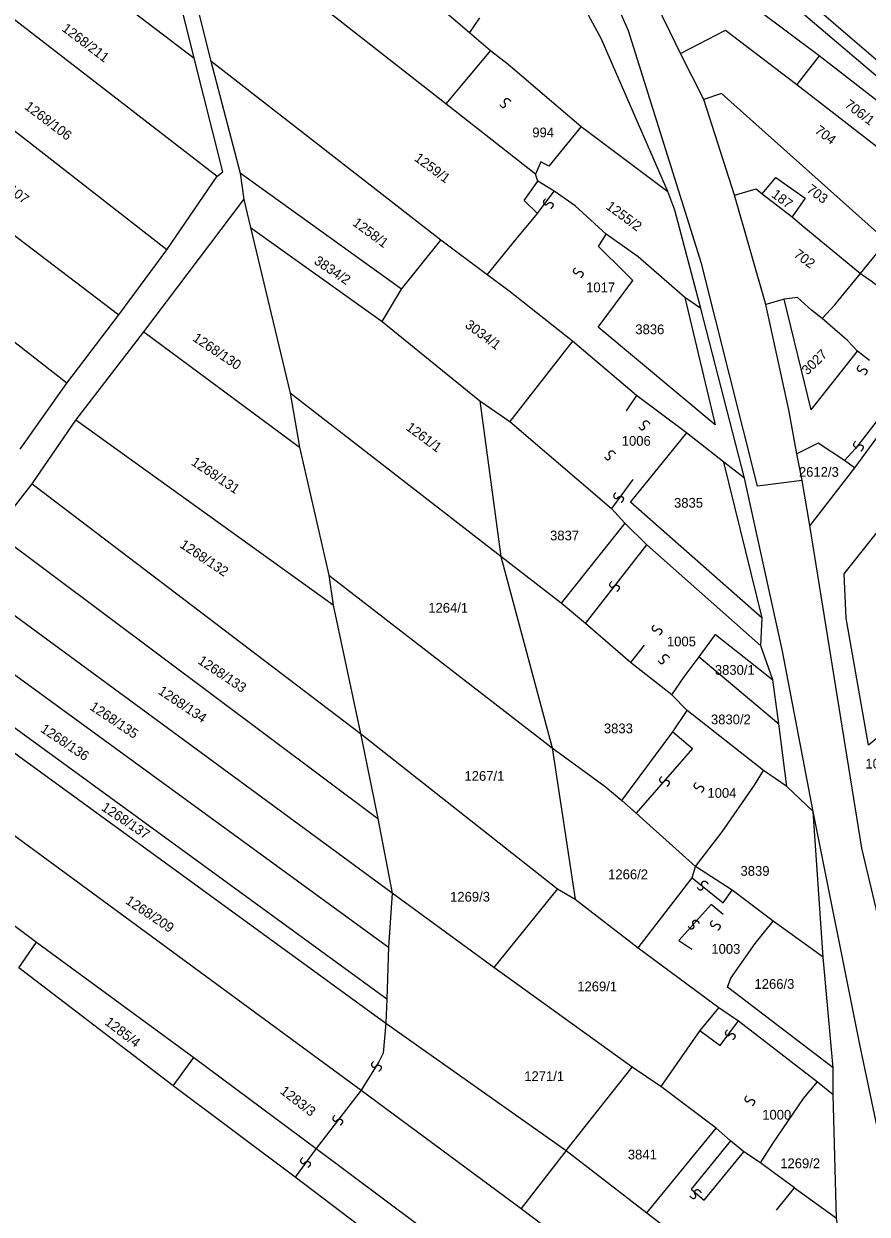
# Model space of a CAD drawing. Extents: x -581999 to -572728, y -1219553 to -1212032.
# Drawn here: x -577907.8 to -577734.8, y -1215058.5 to -1214814.1 of the extents above; entities that cross this region are included whole.
import ezdxf

# ---------------------------------------------------------------- set-up
doc = ezdxf.new("R2010")
doc.units = 0
for name, color, linetype in [('Vrstva 1', 7, 'Continuous'), ('Vrstva 2', 7, 'Continuous'), ('Vrstva 4', 7, 'Continuous'), ('Vrstva 6', 7, 'Continuous')]:
    doc.layers.add(name, color=color, linetype=linetype)

msp = doc.modelspace()

# ---------------------------------------------------------------- linework, layer by layer
at = {"layer": 'Vrstva 1'}
for p, q in [((-577805.154, -1214850.428), (-577802.393, -1214846.429)), ((-577802.455, -1214853.067), (-577805.154, -1214850.428)), ((-577769.288, -1214944.062), (-577752.916, -1214957.844)), ((-577744.997, -1215031.305), (-577741.783, -1215033.863)), ((-577838.633, -1215032.986), (-577805.767, -1215057.281)), ((-577796.548, -1215045.385), (-577805.767, -1215057.281)), ((-577749.734, -1215053.023), (-577741.1, -1215059.241)), ((-577805.767, -1215057.281), (-577776.782, -1215079.289))]:
    msp.add_line(p, q, dxfattribs=at)
for points in [[(-577872.881, -1214821.167), (-577881.879, -1214784.766), (-577891.885, -1214776.612), (-577906.301, -1214795.655)], [(-577821.28, -1214830.565), (-577878.507, -1214785.689)], [(-577878.507, -1214785.689), (-577869.457, -1214821.833)], [(-577717.101, -1214835.147), (-577773.13, -1214787)], [(-577906.301, -1214795.655), (-577872.881, -1214821.167)], [(-577789.366, -1214817.133), (-577800.849, -1214795.966)], [(-577770.074, -1214801.603), (-577765.899, -1214796.69), (-577721.694, -1214834.344), (-577718.663, -1214836.797)], [(-577744.685, -1214820.71), (-577770.074, -1214801.603)], [(-577775.319, -1214815.749), (-577778.369, -1214809.409), (-577781.422, -1214803.251)], [(-577916.139, -1214808.272), (-577868.169, -1214845.419)], [(-577824.804, -1214808.7), (-577816.402, -1214815.913)], [(-577816.402, -1214815.913), (-577812.087, -1214819.635)], [(-577775.677, -1214848.564), (-577789.366, -1214817.133)], [(-577773.096, -1214820.208), (-577775.319, -1214815.749)], [(-577773.096, -1214820.208), (-577763.871, -1214815.445), (-577749.226, -1214826.599)], [(-577812.087, -1214819.635), (-577821.28, -1214830.565)], [(-577812.087, -1214819.635), (-577808.453, -1214822.43)], [(-577768.339, -1214829.671), (-577773.096, -1214820.208)], [(-577868.169, -1214845.419), (-577867.027, -1214844.505), (-577872.881, -1214821.167)], [(-577869.457, -1214821.833), (-577863.423, -1214844.776)], [(-577822.295, -1214858.556), (-577869.457, -1214821.833)], [(-577808.453, -1214822.43), (-577793.468, -1214835.222)], [(-577744.685, -1214820.71), (-577749.226, -1214826.599)], [(-577720.879, -1214839.207), (-577744.685, -1214820.71)], [(-577878.466, -1214860.562), (-577926.666, -1214822.96)], [(-577749.226, -1214826.599), (-577723.731, -1214846.371)], [(-577730.767, -1214858.778), (-577764.668, -1214828.469), (-577768.339, -1214829.671)], [(-577762.008, -1214849.341), (-577768.339, -1214829.671)], [(-577802.883, -1214844.996), (-577821.28, -1214830.565)], [(-577937.19, -1214836.724), (-577888.302, -1214873.863)], [(-577793.468, -1214835.222), (-577800.128, -1214843.356), (-577801.768, -1214842.475)], [(-577793.468, -1214835.222), (-577775.677, -1214848.564)], [(-577801.768, -1214842.475), (-577802.883, -1214844.996)], [(-577878.466, -1214860.562), (-577868.169, -1214845.419)], [(-577830.352, -1214868.618), (-577863.423, -1214844.776)], [(-577863.423, -1214844.776), (-577862.722, -1214850.232)], [(-577799.024, -1214848.482), (-577802.393, -1214846.429), (-577802.883, -1214844.996)], [(-577756.338, -1214849.025), (-577753.571, -1214845.72), (-577747.56, -1214849.959), (-577750.211, -1214853.736)], [(-577794.71, -1214851.511), (-577799.024, -1214848.482)], [(-577768.947, -1214872.584), (-577774.255, -1214852.389), (-577775.677, -1214848.564)], [(-577762.008, -1214849.341), (-577757.6, -1214848.009), (-577756.338, -1214849.025)], [(-577755.598, -1214871.752), (-577762.008, -1214849.341)], [(-577756.338, -1214849.025), (-577750.211, -1214853.736)], [(-577898.986, -1214887.922), (-577947.403, -1214850.101)], [(-577883.226, -1214877.35), (-577862.722, -1214850.232)], [(-577862.722, -1214850.232), (-577861.33, -1214855.947)], [(-577788.355, -1214857.319), (-577794.71, -1214851.511)], [(-577806.799, -1214858.337), (-577802.455, -1214853.067)], [(-577750.211, -1214853.736), (-577748.23, -1214855.49)], [(-577861.33, -1214855.947), (-577834.338, -1214875.209)], [(-577861.33, -1214855.947), (-577853.18, -1214889.973)], [(-577748.23, -1214855.49), (-577736.161, -1214865.367)], [(-577830.352, -1214868.618), (-577822.295, -1214858.556)], [(-577812.743, -1214865.669), (-577822.295, -1214858.556)], [(-577812.743, -1214865.669), (-577806.799, -1214858.337)], [(-577789.957, -1214859.843), (-577788.355, -1214857.319)], [(-577781.771, -1214861.977), (-577788.355, -1214857.319)], [(-577736.161, -1214865.367), (-577730.767, -1214858.778)], [(-577888.302, -1214873.863), (-577878.466, -1214860.562)], [(-577784.584, -1214865.104), (-577789.957, -1214859.843)], [(-577772.241, -1214870.342), (-577781.771, -1214861.977)], [(-577808.33, -1214868.935), (-577812.743, -1214865.669)], [(-577790.014, -1214876.435), (-577782.896, -1214866.833), (-577784.584, -1214865.104)], [(-577741.431, -1214871.84), (-577736.161, -1214865.367)], [(-577736.161, -1214865.367), (-577735.06, -1214866.132)], [(-577735.06, -1214866.132), (-577733.959, -1214866.896), (-577726.213, -1214872.899)], [(-577834.338, -1214875.209), (-577830.352, -1214868.618)], [(-577795.272, -1214879.265), (-577808.33, -1214868.935)], [(-577772.241, -1214870.342), (-577765.961, -1214896.423), (-577790.014, -1214876.435)], [(-577768.947, -1214872.584), (-577772.241, -1214870.342)], [(-577751.809, -1214870.652), (-577755.598, -1214871.752)], [(-577746.217, -1214872.888), (-577749.098, -1214870.305), (-577751.809, -1214870.652)], [(-577746.292, -1214893.355), (-577751.809, -1214870.652)], [(-577898.986, -1214887.922), (-577888.302, -1214873.863)], [(-577759.948, -1214907.393), (-577768.947, -1214872.584)], [(-577749.214, -1214902.401), (-577750.888, -1214893.394), (-577755.598, -1214871.752)], [(-577744.054, -1214874.641), (-577746.217, -1214872.888)], [(-577744.054, -1214874.641), (-577741.431, -1214871.84)], [(-577834.338, -1214875.209), (-577814.262, -1214891.549)], [(-577738.832, -1214879.162), (-577744.054, -1214874.641)], [(-577897.176, -1214895.462), (-577883.226, -1214877.35)], [(-577883.226, -1214877.35), (-577851.24, -1214901.065)], [(-577795.272, -1214879.265), (-577808.13, -1214895.741)], [(-577782.109, -1214890.419), (-577795.272, -1214879.265)], [(-577746.292, -1214893.355), (-577736.764, -1214881.349)], [(-577736.764, -1214881.349), (-577738.832, -1214879.162)], [(-577734.33, -1214883.219), (-577736.764, -1214881.349)], [(-577908.594, -1214901.454), (-577898.986, -1214887.922)], [(-577809.986, -1214923.459), (-577853.18, -1214889.973)], [(-577853.18, -1214889.973), (-577851.24, -1214901.065)], [(-577771.896, -1214898.095), (-577782.109, -1214890.419)], [(-577726.097, -1214889.907), (-577737.394, -1214905.307)], [(-577814.262, -1214891.549), (-577808.13, -1214895.741)], [(-577814.262, -1214891.549), (-577809.986, -1214923.459)], [(-577906.098, -1214908.537), (-577897.176, -1214895.462)], [(-577844.378, -1214933.467), (-577897.176, -1214895.462)], [(-577808.13, -1214895.741), (-577787.252, -1214913.628)], [(-577771.896, -1214898.095), (-577783.379, -1214912.272), (-577756.365, -1214936.081)], [(-577764.181, -1214904.139), (-577771.896, -1214898.095)], [(-577744.872, -1214900.225), (-577749.214, -1214902.401)], [(-577739.465, -1214903.76), (-577744.872, -1214900.225)], [(-577851.24, -1214901.065), (-577845.255, -1214927.289)], [(-577748.112, -1214907.863), (-577749.214, -1214902.401)], [(-577756.365, -1214936.081), (-577764.181, -1214904.139)], [(-577759.948, -1214907.393), (-577764.181, -1214904.139)], [(-577737.394, -1214905.307), (-577746.549, -1214917.111)], [(-577737.394, -1214905.307), (-577739.465, -1214903.76)], [(-577745.87, -1214975.785), (-577752.202, -1214942.91), (-577759.948, -1214907.393)], [(-577746.549, -1214917.111), (-577748.112, -1214907.863)], [(-577913.873, -1214918.393), (-577906.098, -1214908.537)], [(-577906.098, -1214908.537), (-577838.722, -1214959.823)], [(-577721.217, -1214951.277), (-577734.554, -1214962.178), (-577739.113, -1214936.121), (-577739.514, -1214927.04), (-577725.038, -1214908.739)], [(-577787.252, -1214913.628), (-577784.532, -1214916.641)], [(-577784.532, -1214916.641), (-577797.58, -1214933.029)], [(-577784.532, -1214916.641), (-577779.996, -1214921.049)], [(-577725.151, -1215028.582), (-577735.904, -1214983.329), (-577746.549, -1214917.111)], [(-577913.873, -1214918.393), (-577835.19, -1214977.265)], [(-577779.996, -1214921.049), (-577756.613, -1214941.836)], [(-577797.58, -1214933.029), (-577809.986, -1214923.459)], [(-577809.986, -1214923.459), (-577799.455, -1214962.724)], [(-577832.228, -1214992.583), (-577920.733, -1214927.564)], [(-577845.255, -1214927.289), (-577799.455, -1214962.724)], [(-577845.255, -1214927.289), (-577844.378, -1214933.467)], [(-577844.378, -1214933.467), (-577838.722, -1214959.823)], [(-577792.588, -1214937.209), (-577797.58, -1214933.029)], [(-577926.452, -1214935.59), (-577832.981, -1215003.643)], [(-577774.893, -1214951.838), (-577783.351, -1214945.243), (-577792.588, -1214937.209)], [(-577756.613, -1214941.836), (-577756.365, -1214936.081)], [(-577772.331, -1214948.175), (-577769.288, -1214944.062), (-577765.931, -1214939.469)], [(-577765.931, -1214939.469), (-577754.136, -1214948.76)], [(-577754.136, -1214948.76), (-577756.613, -1214941.836)], [(-577833.373, -1215014.342), (-577931.711, -1214942.697)], [(-577934.388, -1214945.892), (-577833.569, -1215019.238)], [(-577774.893, -1214951.838), (-577772.331, -1214948.175)], [(-577751.305, -1214970.645), (-577752.916, -1214957.844), (-577754.136, -1214948.76)], [(-577771.72, -1214955.083), (-577774.893, -1214951.838)], [(-577942.23, -1214956.913), (-577838.633, -1215032.986)], [(-577774.645, -1214959.44), (-577771.72, -1214955.083)], [(-577756.069, -1214967.39), (-577771.72, -1214955.083)], [(-577785.145, -1214973.548), (-577774.645, -1214959.44)], [(-577838.722, -1214959.823), (-577798.346, -1214991.679)], [(-577838.722, -1214959.823), (-577835.19, -1214977.265)], [(-577799.455, -1214962.724), (-577788.541, -1214970.706)], [(-577799.455, -1214962.724), (-577794.712, -1214993.776)], [(-577950.919, -1214968.374), (-577905.234, -1215002.63)], [(-577757.899, -1214970.37), (-577756.069, -1214967.39)], [(-577751.305, -1214970.645), (-577756.069, -1214967.39)], [(-577788.541, -1214970.706), (-577785.145, -1214973.548)], [(-577764.529, -1214979.993), (-577757.899, -1214970.37)], [(-577745.87, -1214975.785), (-577751.305, -1214970.645)], [(-577785.145, -1214973.548), (-577782.229, -1214976.12)], [(-577782.229, -1214976.12), (-577779.392, -1214978.712)], [(-577743.829, -1215005.717), (-577745.87, -1214975.785)], [(-577723.919, -1215082.491), (-577736.309, -1215023.635), (-577745.87, -1214975.785)], [(-577835.19, -1214977.265), (-577832.228, -1214992.583)], [(-577779.392, -1214978.712), (-577770.013, -1214987.092)], [(-577770.013, -1214987.092), (-577764.529, -1214979.993)], [(-577770.703, -1214989.389), (-577770.013, -1214987.092)], [(-577762.525, -1214991.974), (-577770.013, -1214987.092)], [(-577781.781, -1215003.757), (-577770.703, -1214989.389)], [(-577832.228, -1214992.583), (-577832.981, -1215003.643)], [(-577811.392, -1215007.847), (-577832.228, -1214992.583)], [(-577798.346, -1214991.679), (-577811.392, -1215007.847)], [(-577798.346, -1214991.679), (-577794.712, -1214993.776)], [(-577754.114, -1214998.324), (-577762.525, -1214991.974)], [(-577794.712, -1214993.776), (-577781.781, -1215003.757)], [(-577757.769, -1215002.902), (-577754.114, -1214998.324)], [(-577743.829, -1215005.717), (-577754.114, -1214998.324)], [(-577908.852, -1215007.879), (-577905.234, -1215002.63)], [(-577905.234, -1215002.63), (-577872.974, -1215026.324)], [(-577762.797, -1215010.002), (-577757.769, -1215002.902)], [(-577832.981, -1215003.643), (-577833.373, -1215014.342)], [(-577781.781, -1215003.757), (-577765.223, -1215016.061)], [(-577741.763, -1215028.425), (-577743.829, -1215005.717)], [(-577877.169, -1215032.139), (-577908.852, -1215007.879)], [(-577783.029, -1215028.281), (-577811.392, -1215007.847)], [(-577741.763, -1215028.425), (-577763.485, -1215011.839), (-577762.797, -1215010.002)], [(-577833.373, -1215014.342), (-577833.569, -1215019.238)], [(-577765.223, -1215016.061), (-577769.148, -1215020.777)], [(-577765.223, -1215016.061), (-577761.237, -1215018.756)], [(-577833.569, -1215019.238), (-577796.548, -1215045.385)], [(-577761.237, -1215018.756), (-577744.997, -1215031.305)], [(-577769.148, -1215020.777), (-577777.13, -1215032.23)], [(-577877.169, -1215032.139), (-577872.974, -1215026.324)], [(-577872.974, -1215026.324), (-577847.84, -1215044.937), (-577785.524, -1215091.587)], [(-577796.548, -1215045.385), (-577783.029, -1215028.281)], [(-577777.13, -1215032.23), (-577783.029, -1215028.281)], [(-577741.783, -1215033.863), (-577741.763, -1215028.425)], [(-577775.2, -1215109.258), (-577852.17, -1215050.829), (-577877.169, -1215032.139)], [(-577765.792, -1215040.814), (-577777.13, -1215032.23)], [(-577747.876, -1215034.73), (-577744.997, -1215031.305)], [(-577754.179, -1215043.933), (-577747.876, -1215034.73)], [(-577736.638, -1215091.441), (-577741.1, -1215059.241), (-577741.783, -1215033.863)], [(-577779.991, -1215058.141), (-577765.792, -1215040.814)], [(-577762.845, -1215043.364), (-577765.792, -1215040.814)], [(-577760.125, -1215045.681), (-577762.845, -1215043.364)], [(-577756.701, -1215047.904), (-577754.179, -1215043.933)], [(-577796.548, -1215045.385), (-577779.991, -1215058.141)], [(-577756.701, -1215047.904), (-577760.125, -1215045.681)], [(-577754.022, -1215049.915), (-577756.701, -1215047.904)], [(-577749.734, -1215053.023), (-577754.022, -1215049.915)], [(-577779.991, -1215058.141), (-577759.359, -1215074.139)]]:
    msp.add_lwpolyline(points, dxfattribs=at)
at = {"layer": 'Vrstva 4'}
for p, q in [((-577780.547, -1214941.639), (-577783.351, -1214945.243)), ((-577766.821, -1214994.916), (-577773.433, -1215002.296)), ((-577764.355, -1214996.976), (-577766.821, -1214994.916)), ((-577773.433, -1215002.296), (-577770.797, -1215004.053)), ((-577838.633, -1215032.986), (-577847.84, -1215044.937)), ((-577847.84, -1215044.937), (-577852.17, -1215050.829))]:
    msp.add_line(p, q, dxfattribs=at)
for points in [[(-577748.112, -1214907.863), (-577757.342, -1214909.066), (-577768.775, -1214863.348), (-577783.781, -1214815.615), (-577793.837, -1214792.623), (-577805.805, -1214772.945), (-577829.636, -1214736.584), (-577832.529, -1214732.708), (-577835.422, -1214734.446), (-577847.175, -1214721.492)], [(-577814.321, -1214812.912), (-577816.402, -1214815.913)], [(-577802.455, -1214853.067), (-577799.024, -1214848.482)], [(-577782.109, -1214890.419), (-577784.225, -1214893.607)], [(-577732.932, -1214895.851), (-577737.198, -1214901.285)], [(-577737.198, -1214901.285), (-577739.465, -1214903.76)], [(-577782.907, -1214907.669), (-577787.252, -1214913.628)], [(-577792.588, -1214937.209), (-577779.996, -1214921.049)], [(-577774.645, -1214959.44), (-577770.659, -1214962.903), (-577782.229, -1214976.12)], [(-577770.703, -1214989.389), (-577764.374, -1214994.551), (-577762.525, -1214991.974)], [(-577833.569, -1215019.238), (-577834.126, -1215025.399), (-577835.028, -1215027.207)], [(-577769.148, -1215020.777), (-577764.947, -1215023.843), (-577761.237, -1215018.756)], [(-577835.028, -1215027.207), (-577838.633, -1215032.986)], [(-577762.845, -1215043.364), (-577770.884, -1215053.298), (-577768.258, -1215055.599), (-577760.125, -1215045.681)], [(-577753.405, -1215057.595), (-577749.734, -1215053.023)]]:
    msp.add_lwpolyline(points, dxfattribs=at)
at = {"layer": 'Vrstva 6'}
for points in [[(-577810.196, -1214830.73), (-577809.716, -1214831.437), (-577809.022, -1214831.126), (-577808.945, -1214830.726), (-577809.181, -1214830.381), (-577809.266, -1214830.049), (-577809.184, -1214829.759), (-577809.04, -1214829.579), (-577808.804, -1214829.451), (-577808.439, -1214829.487), (-577808.012, -1214829.926), (-577807.957, -1214830.099)], [(-577800.815, -1214850.044), (-577801.402, -1214850.666), (-577800.947, -1214851.275), (-577800.541, -1214851.263), (-577800.255, -1214850.958), (-577799.949, -1214850.804), (-577799.649, -1214850.82), (-577799.442, -1214850.922), (-577799.266, -1214851.125), (-577799.221, -1214851.489), (-577799.556, -1214852.001), (-577799.714, -1214852.093)], [(-577794.68, -1214864.197), (-577795.267, -1214864.819), (-577794.812, -1214865.428), (-577794.406, -1214865.416), (-577794.12, -1214865.111), (-577793.814, -1214864.957), (-577793.514, -1214864.973), (-577793.307, -1214865.075), (-577793.131, -1214865.278), (-577793.086, -1214865.642), (-577793.421, -1214866.154), (-577793.579, -1214866.246)], [(-577736.42, -1214884.2), (-577737.007, -1214884.822), (-577736.552, -1214885.431), (-577736.146, -1214885.419), (-577735.86, -1214885.114), (-577735.554, -1214884.96), (-577735.254, -1214884.976), (-577735.047, -1214885.078), (-577734.871, -1214885.281), (-577734.826, -1214885.645), (-577735.161, -1214886.157), (-577735.319, -1214886.249)], [(-577781.668, -1214896.88), (-577781.188, -1214897.587), (-577780.494, -1214897.276), (-577780.417, -1214896.876), (-577780.653, -1214896.531), (-577780.738, -1214896.199), (-577780.656, -1214895.909), (-577780.512, -1214895.729), (-577780.276, -1214895.601), (-577779.911, -1214895.637), (-577779.484, -1214896.076), (-577779.429, -1214896.249)], [(-577737.205, -1214899.793), (-577737.792, -1214900.415), (-577737.337, -1214901.024), (-577736.931, -1214901.012), (-577736.645, -1214900.707), (-577736.339, -1214900.553), (-577736.039, -1214900.569), (-577735.832, -1214900.671), (-577735.656, -1214900.874), (-577735.611, -1214901.238), (-577735.946, -1214901.75), (-577736.104, -1214901.842)], [(-577788.723, -1214903.034), (-577788.243, -1214903.741), (-577787.549, -1214903.43), (-577787.472, -1214903.03), (-577787.708, -1214902.685), (-577787.793, -1214902.353), (-577787.711, -1214902.063), (-577787.567, -1214901.883), (-577787.331, -1214901.755), (-577786.966, -1214901.791), (-577786.539, -1214902.23), (-577786.484, -1214902.403)], [(-577786.397, -1214910.349), (-577786.984, -1214910.971), (-577786.529, -1214911.58), (-577786.123, -1214911.568), (-577785.837, -1214911.263), (-577785.531, -1214911.109), (-577785.231, -1214911.125), (-577785.024, -1214911.227), (-577784.848, -1214911.43), (-577784.803, -1214911.794), (-577785.138, -1214912.306), (-577785.296, -1214912.398)], [(-577787.245, -1214928.581), (-577787.832, -1214929.203), (-577787.377, -1214929.812), (-577786.971, -1214929.8), (-577786.685, -1214929.495), (-577786.379, -1214929.341), (-577786.079, -1214929.357), (-577785.872, -1214929.459), (-577785.696, -1214929.662), (-577785.651, -1214930.026), (-577785.986, -1214930.538), (-577786.144, -1214930.63)], [(-577778.517, -1214937.534), (-577779.104, -1214938.156), (-577778.649, -1214938.765), (-577778.243, -1214938.753), (-577777.957, -1214938.448), (-577777.651, -1214938.294), (-577777.351, -1214938.31), (-577777.144, -1214938.412), (-577776.968, -1214938.615), (-577776.923, -1214938.979), (-577777.258, -1214939.491), (-577777.416, -1214939.583)], [(-577777.68, -1214944.878), (-577777.2, -1214945.585), (-577776.506, -1214945.274), (-577776.429, -1214944.874), (-577776.665, -1214944.529), (-577776.75, -1214944.197), (-577776.668, -1214943.907), (-577776.524, -1214943.727), (-577776.288, -1214943.599), (-577775.923, -1214943.635), (-577775.496, -1214944.074), (-577775.441, -1214944.247)], [(-577776.983, -1214968.609), (-577777.57, -1214969.231), (-577777.115, -1214969.84), (-577776.709, -1214969.828), (-577776.423, -1214969.523), (-577776.117, -1214969.369), (-577775.817, -1214969.385), (-577775.61, -1214969.487), (-577775.434, -1214969.69), (-577775.389, -1214970.054), (-577775.724, -1214970.566), (-577775.882, -1214970.658)], [(-577769.928, -1214969.84), (-577770.515, -1214970.462), (-577770.06, -1214971.071), (-577769.654, -1214971.059), (-577769.368, -1214970.754), (-577769.062, -1214970.6), (-577768.762, -1214970.616), (-577768.555, -1214970.718), (-577768.379, -1214970.921), (-577768.334, -1214971.285), (-577768.669, -1214971.797), (-577768.827, -1214971.889)], [(-577769.704, -1214991.338), (-577769.224, -1214992.045), (-577768.53, -1214991.734), (-577768.453, -1214991.334), (-577768.689, -1214990.989), (-577768.774, -1214990.657), (-577768.692, -1214990.367), (-577768.548, -1214990.187), (-577768.312, -1214990.059), (-577767.947, -1214990.095), (-577767.52, -1214990.534), (-577767.465, -1214990.707)], [(-577771.545, -1214999.338), (-577771.065, -1215000.045), (-577770.371, -1214999.734), (-577770.294, -1214999.334), (-577770.53, -1214998.989), (-577770.615, -1214998.657), (-577770.533, -1214998.367), (-577770.389, -1214998.187), (-577770.153, -1214998.059), (-577769.788, -1214998.095), (-577769.361, -1214998.534), (-577769.306, -1214998.707)], [(-577766.553, -1214998.146), (-577767.14, -1214998.768), (-577766.685, -1214999.377), (-577766.279, -1214999.365), (-577765.993, -1214999.06), (-577765.687, -1214998.906), (-577765.387, -1214998.922), (-577765.18, -1214999.024), (-577765.004, -1214999.227), (-577764.959, -1214999.591), (-577765.294, -1215000.103), (-577765.452, -1215000.195)], [(-577763.486, -1215020.607), (-577764.073, -1215021.229), (-577763.618, -1215021.838), (-577763.212, -1215021.826), (-577762.926, -1215021.521), (-577762.62, -1215021.367), (-577762.32, -1215021.383), (-577762.113, -1215021.485), (-577761.937, -1215021.688), (-577761.892, -1215022.052), (-577762.227, -1215022.564), (-577762.385, -1215022.656)], [(-577836.092, -1215027.086), (-577836.679, -1215027.708), (-577836.224, -1215028.317), (-577835.818, -1215028.305), (-577835.532, -1215028), (-577835.226, -1215027.846), (-577834.926, -1215027.862), (-577834.719, -1215027.964), (-577834.543, -1215028.167), (-577834.498, -1215028.531), (-577834.833, -1215029.043), (-577834.991, -1215029.135)], [(-577759.498, -1215034.145), (-577760.085, -1215034.767), (-577759.63, -1215035.376), (-577759.224, -1215035.364), (-577758.938, -1215035.059), (-577758.632, -1215034.905), (-577758.332, -1215034.921), (-577758.125, -1215035.023), (-577757.949, -1215035.226), (-577757.904, -1215035.59), (-577758.239, -1215036.102), (-577758.397, -1215036.194)], [(-577844.031, -1215038.146), (-577844.618, -1215038.768), (-577844.163, -1215039.377), (-577843.757, -1215039.365), (-577843.471, -1215039.06), (-577843.165, -1215038.906), (-577842.865, -1215038.922), (-577842.658, -1215039.024), (-577842.482, -1215039.227), (-577842.437, -1215039.591), (-577842.772, -1215040.103), (-577842.93, -1215040.195)], [(-577850.63, -1215046.828), (-577851.217, -1215047.45), (-577850.762, -1215048.059), (-577850.356, -1215048.047), (-577850.07, -1215047.742), (-577849.764, -1215047.588), (-577849.464, -1215047.604), (-577849.257, -1215047.706), (-577849.081, -1215047.909), (-577849.036, -1215048.273), (-577849.371, -1215048.785), (-577849.529, -1215048.877)], [(-577771.161, -1215054.664), (-577770.681, -1215055.371), (-577769.987, -1215055.06), (-577769.91, -1215054.66), (-577770.146, -1215054.315), (-577770.231, -1215053.983), (-577770.149, -1215053.693), (-577770.005, -1215053.513), (-577769.769, -1215053.385), (-577769.404, -1215053.421), (-577768.977, -1215053.86), (-577768.922, -1215054.033)]]:
    msp.add_open_spline(points, degree=2, dxfattribs=at)

# ---------------------------------------------------------------- texts
at = {"layer": 'Vrstva 2'}
for s, rotation, p in [('1268/211', 322.87453, (-577900.173, -1214815.449)), ('706/1', 322.91464, (-577739.589, -1214831.075)), ('1268/106', 322.87453, (-577907.847, -1214831.465)), ('704', 322.91464, (-577745.718, -1214836.389)), ('1259/1', 323.42903, (-577827.869, -1214842.085)), ('1268/107', 322.87453, (-577916.627, -1214844.505)), ('703', 323.42903, (-577747.398, -1214848.508)), ('187', 323.42903, (-577754.605, -1214849.544)), ('1255/2', 323.42903, (-577788.55, -1214851.962)), ('1258/1', 323.42903, (-577840.542, -1214855.357)), ('3834/2', 326.18252, (-577848.453, -1214863.25)), ('702', 323.42903, (-577750.02, -1214861.81)), ('3034/1', 323.42903, (-577817.469, -1214876.293)), ('1268/130', 326.18252, (-577873.353, -1214879.069)), ('3027', 44.12935, (-577747.077, -1214886.345)), ('1261/1', 323.42903, (-577829.591, -1214897.331)), ('1268/131', 326.18252, (-577873.661, -1214904.52)), ('1268/132', 326.18252, (-577875.99, -1214921.468)), ('1268/133', 326.18252, (-577872.297, -1214945.294)), ('1268/134', 326.18252, (-577880.449, -1214951.514)), ('1268/135', 326.18252, (-577894.467, -1214954.758)), ('1268/136', 326.18252, (-577904.563, -1214959.308)), ('1268/137', 326.18252, (-577892.086, -1214975.405)), ('1268/209', 326.18252, (-577887.147, -1214994.562)), ('1285/4', 322.32175, (-577891.384, -1215019.364)), ('1283/3', 322.32175, (-577855.406, -1215033.512))]:
    msp.add_text(s, height=2, rotation=rotation, dxfattribs=at).set_placement(p)
for s, p in [('994', (-577803.513, -1214837.438)), ('1017', (-577792.473, -1214869.234)), ('3836', (-577782.372, -1214877.849)), ('1006', (-577785.157, -1214900.738)), ('2612/3', (-577748.807, -1214907.112)), ('3835', (-577774.431, -1214913.457)), ('3837', (-577799.863, -1214920.159)), ('1264/1', (-577824.854, -1214935.001)), ('1005', (-577775.887, -1214941.904)), ('3830/1', (-577766.056, -1214947.751)), ('3830/2', (-577766.86, -1214957.905)), ('3833', (-577788.823, -1214959.751)), ('1060/1', (-577735.171, -1214966.985)), ('1267/1', (-577817.428, -1214969.511)), ('1004', (-577767.578, -1214972.995)), ('1266/2', (-577787.949, -1214989.705)), ('3839', (-577760.796, -1214988.996)), ('1269/3', (-577820.375, -1214994.306)), ('1003', (-577766.776, -1215005.008)), ('1269/1', (-577794.288, -1215012.712)), ('1266/3', (-577757.927, -1215012.2)), ('1271/1', (-577805.162, -1215031.117)), ('1000', (-577756.339, -1215039.041)), ('3841', (-577783.909, -1215047.208)), ('1269/2', (-577752.641, -1215049.011))]:
    msp.add_text(s, height=2, dxfattribs=at).set_placement(p)

doc.saveas('drawing.dxf')
